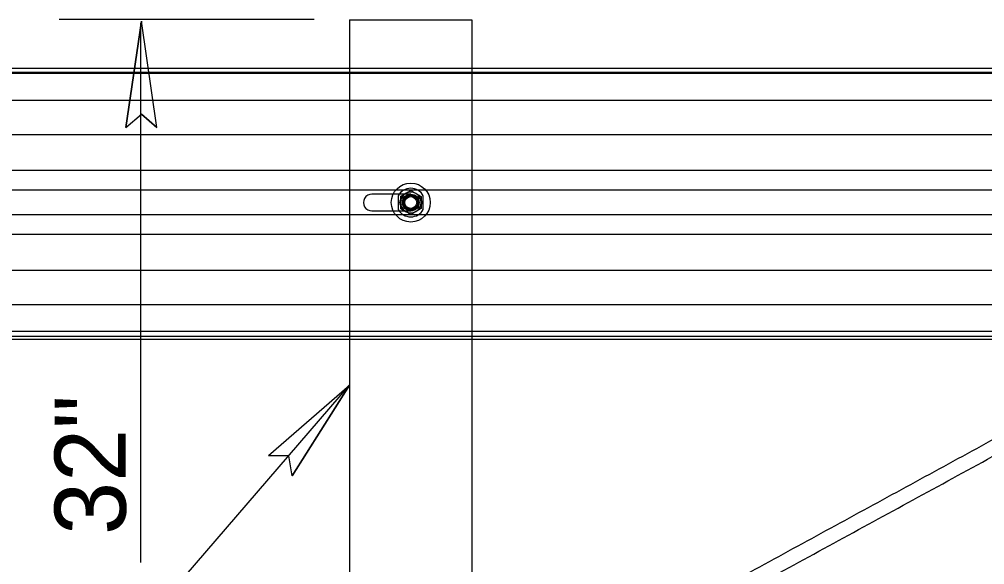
# Model space of a CAD drawing. Extents: x 12.2 to 54.5, y -7.8 to 16.1.
# Drawn here: x 13.367 to 14.18, y 14.798 to 15.257 of the extents above; entities that cross this region are included whole.
import ezdxf

# ---------------------------------------------------------------- set-up
doc = ezdxf.new("R2010")
doc.units = 0
for name, color, linetype in [('BORD-LINE', 7, 'Continuous'), ('DETL-DIMS', 7, 'Continuous'), ('DETL-NOTE', 7, 'Continuous')]:
    doc.layers.add(name, color=color, linetype=linetype)

msp = doc.modelspace()

# ---------------------------------------------------------------- linework, layer by layer
at = {"layer": 'BORD-LINE'}
for p, q in [((13.64499, 15.2566), (13.64499, 14.67435)), ((13.64499, 15.2566), (13.74802, 15.2566)), ((13.74802, 15.2566), (13.74802, 14.67435)), ((13.64499, 15.21566), (13.10438, 15.21566)), ((13.74802, 15.21566), (13.64499, 15.21566)), ((15.04876, 15.21566), (13.74802, 15.21566)), ((13.64499, 15.21237), (13.10438, 15.21237)), ((13.64499, 15.21142), (13.10438, 15.21142)), ((13.74802, 15.21237), (13.64499, 15.21237)), ((13.74802, 15.21142), (13.64499, 15.21142)), ((15.04839, 15.21237), (13.74802, 15.21237)), ((15.04894, 15.21142), (13.74802, 15.21142)), ((13.64499, 15.18879), (13.10438, 15.18879)), ((13.74802, 15.18879), (13.64499, 15.18879)), ((15.04876, 15.18879), (13.74802, 15.18879)), ((13.64499, 15.15992), (13.1251, 15.15992)), ((13.74802, 15.15992), (13.64499, 15.15992)), ((14.59422, 15.15992), (13.74802, 15.15992)), ((13.64499, 15.12967), (13.15534, 15.12967)), ((13.74802, 15.12967), (13.64499, 15.12967)), ((14.56516, 15.12967), (13.74802, 15.12967)), ((13.64499, 15.11315), (13.16063, 15.11315)), ((13.74802, 15.11315), (13.64499, 15.11315)), ((13.6965, 15.10985), (13.66373, 15.10985)), ((13.68597, 15.10858), (13.68597, 15.09706)), ((13.70704, 15.09706), (13.70704, 15.10858)), ((14.56516, 15.11315), (13.74802, 15.11315)), ((13.64499, 15.0925), (13.16063, 15.0925)), ((13.74802, 15.0925), (13.64499, 15.0925)), ((13.66373, 15.0958), (13.6965, 15.0958)), ((14.55846, 15.0925), (13.74802, 15.0925)), ((13.64499, 15.07597), (13.1544, 15.07597)), ((13.74802, 15.07597), (13.64499, 15.07597)), ((14.52883, 15.07597), (13.74802, 15.07597)), ((13.64499, 15.04573), (13.12416, 15.04573)), ((13.74802, 15.04573), (13.64499, 15.04573)), ((14.4734, 15.04573), (13.74802, 15.04573)), ((13.64499, 15.01685), (13.10438, 15.01685)), ((13.74802, 15.01685), (13.64499, 15.01685)), ((14.42049, 15.01685), (13.74802, 15.01685)), ((13.64499, 14.99422), (13.10438, 14.99422)), ((13.74802, 14.99422), (13.64499, 14.99422)), ((14.37901, 14.99422), (13.74802, 14.99422)), ((13.64499, 14.98999), (13.10438, 14.98999)), ((13.64499, 14.98751), (13.10438, 14.98751)), ((13.74802, 14.98999), (13.64499, 14.98999)), ((13.74802, 14.98751), (13.64499, 14.98751)), ((14.37125, 14.98999), (13.74802, 14.98999)), ((14.36671, 14.98751), (13.74802, 14.98751))]:
    msp.add_line(p, q, dxfattribs=at)
for points in [[(13.6965, 15.10868), (13.69488, 15.10859), (13.6933, 15.10832), (13.69182, 15.10789), (13.69048, 15.10731), (13.68933, 15.10658), (13.68839, 15.10575), (13.6877, 15.10482), (13.68728, 15.10384), (13.68714, 15.10282), (13.68728, 15.10181), (13.6877, 15.10082), (13.68839, 15.0999), (13.68933, 15.09906), (13.69048, 15.09834), (13.69182, 15.09775), (13.6933, 15.09732), (13.69488, 15.09706), (13.6965, 15.09697)], [(13.6965, 15.09697), (13.69813, 15.09706), (13.69971, 15.09732), (13.70119, 15.09775), (13.70252, 15.09834), (13.70368, 15.09906), (13.70462, 15.0999), (13.70531, 15.10082), (13.70573, 15.10181), (13.70587, 15.10282), (13.70573, 15.10384), (13.70531, 15.10482), (13.70462, 15.10575), (13.70368, 15.10658), (13.70252, 15.10731), (13.70119, 15.10789), (13.69971, 15.10832), (13.69813, 15.10859), (13.6965, 15.10868)]]:
    msp.add_lwpolyline(points, dxfattribs=at)
for centre, radius in [((13.69651, 15.10282), 0.01639), ((13.69651, 15.10282), 0.00702), ((13.6965, 15.10282), 0.00614), ((13.6965, 15.10282), 0.00585), ((13.69651, 15.10282), 0.00498)]:
    msp.add_circle(centre, radius, dxfattribs=at)
for centre, radius, start, end in [((13.66373, 15.10282), 0.00702, 89.99821, 270.00179), ((13.69651, 15.10282), 0.01201, 28.65368, 151.34632), ((13.69651, 15.10282), 0.00879, 120.00351, 179.99356), ((13.69651, 15.10282), 0.00878, 59.9996, 120.0004), ((13.69651, 15.10282), 0.00643, 57.87294, 122.12706), ((13.6965, 15.10282), 0.00879, 0.00644, 59.99649), ((13.69651, 15.10282), 0.00879, 180.00537, 239.99756), ((13.6965, 15.10282), 0.00879, 300.00244, 359.99463), ((13.69651, 15.10282), 0.01201, 208.65297, 331.34703), ((13.69651, 15.10282), 0.00878, 239.99746, 300.00254), ((13.69651, 15.10282), 0.00643, 237.87294, 302.12706)]:
    msp.add_arc(centre, radius, start, end, dxfattribs=at)
for points, degree in [([(13.68772, 15.10789), (13.68841, 15.10829), (13.68986, 15.10913), (13.69132, 15.10997), (13.69209, 15.11042), (13.69211, 15.11043)], 3), ([(13.68772, 15.10789), (13.68772, 15.10746), (13.68772, 15.10642), (13.68772, 15.10473), (13.68772, 15.10347), (13.68772, 15.10282)], 3), ([(13.69211, 15.11043), (13.69272, 15.11078), (13.69395, 15.11149), (13.69541, 15.11233), (13.69626, 15.11283), (13.6965, 15.11297)], 3), ([(13.6965, 15.11297), (13.6972, 15.11257), (13.69864, 15.11173), (13.70011, 15.11089), (13.70088, 15.11044), (13.7009, 15.11043)], 3), ([(13.7009, 15.11043), (13.70151, 15.11008), (13.70273, 15.10937), (13.7042, 15.10853), (13.70505, 15.10803), (13.70529, 15.10789)], 3), ([(13.70529, 15.10789), (13.70529, 15.10746), (13.70529, 15.10642), (13.70529, 15.10473), (13.70529, 15.10347), (13.70529, 15.10282)], 3), ([(13.68772, 15.10282), (13.68772, 15.10271), (13.68772, 15.10195), (13.68772, 15.10056), (13.68772, 15.09898), (13.68772, 15.09805), (13.68772, 15.09775)], 3), ([(13.70529, 15.10282), (13.70529, 15.10271), (13.70529, 15.10195), (13.70529, 15.10056), (13.70529, 15.09898), (13.70529, 15.09805), (13.70529, 15.09775)], 3), ([(13.69211, 15.09521), (13.6915, 15.09557), (13.69028, 15.09627), (13.68881, 15.09712), (13.68796, 15.09761), (13.68772, 15.09775)], 3), ([(13.6965, 15.09268), (13.69581, 15.09308), (13.69437, 15.09391), (13.6929, 15.09475), (13.69213, 15.0952), (13.69211, 15.09521)], 3), ([(13.7009, 15.09521), (13.70029, 15.09486), (13.69906, 15.09415), (13.6976, 15.09331), (13.69675, 15.09282), (13.6965, 15.09268)], 3), ([(13.70529, 15.09775), (13.7046, 15.09735), (13.70315, 15.09652), (13.70169, 15.09567), (13.70092, 15.09523), (13.7009, 15.09521)], 3), ([(13.83143, 14.69542), (14.36586, 14.98687)], 1), ([(14.3398, 14.98655), (13.83143, 14.70947)], 1)]:
    msp.add_open_spline(points, degree=degree, dxfattribs=at)
at = {"layer": 'DETL-DIMS'}
for p, q in [((13.40035, 15.25704), (13.61503, 15.25704)), ((13.45648, 15.16598), (13.46968, 15.25558)), ((13.46925, 14.79993), (13.46925, 15.25392)), ((13.48258, 15.16598), (13.46968, 15.25558)), ((13.45648, 15.16598), (13.46968, 15.17708)), ((13.48258, 15.16598), (13.46968, 15.17708)), ((13.49393, 14.77401), (13.64499, 14.9492)), ((13.57671, 14.88977), (13.64499, 14.9492)), ((13.59648, 14.87273), (13.64499, 14.9492)), ((13.57671, 14.88977), (13.59373, 14.88975)), ((13.59648, 14.87273), (13.59373, 14.88975))]:
    msp.add_line(p, q, dxfattribs=at)
for points in [[(13.48258, 15.16598), (13.46968, 15.25558), (13.45648, 15.16598), (13.46968, 15.17708)], [(13.57671, 14.88977), (13.64499, 14.9492), (13.59648, 14.87273), (13.59373, 14.88975)]]:
    msp.add_lwpolyline(points, close=True, dxfattribs=at)

# ---------------------------------------------------------------- texts
at = {"layer": 'DETL-NOTE'}
msp.add_text('32"', height=0.06, rotation=90, dxfattribs=at).set_placement((13.45651, 14.82305))

doc.saveas('drawing.dxf')
